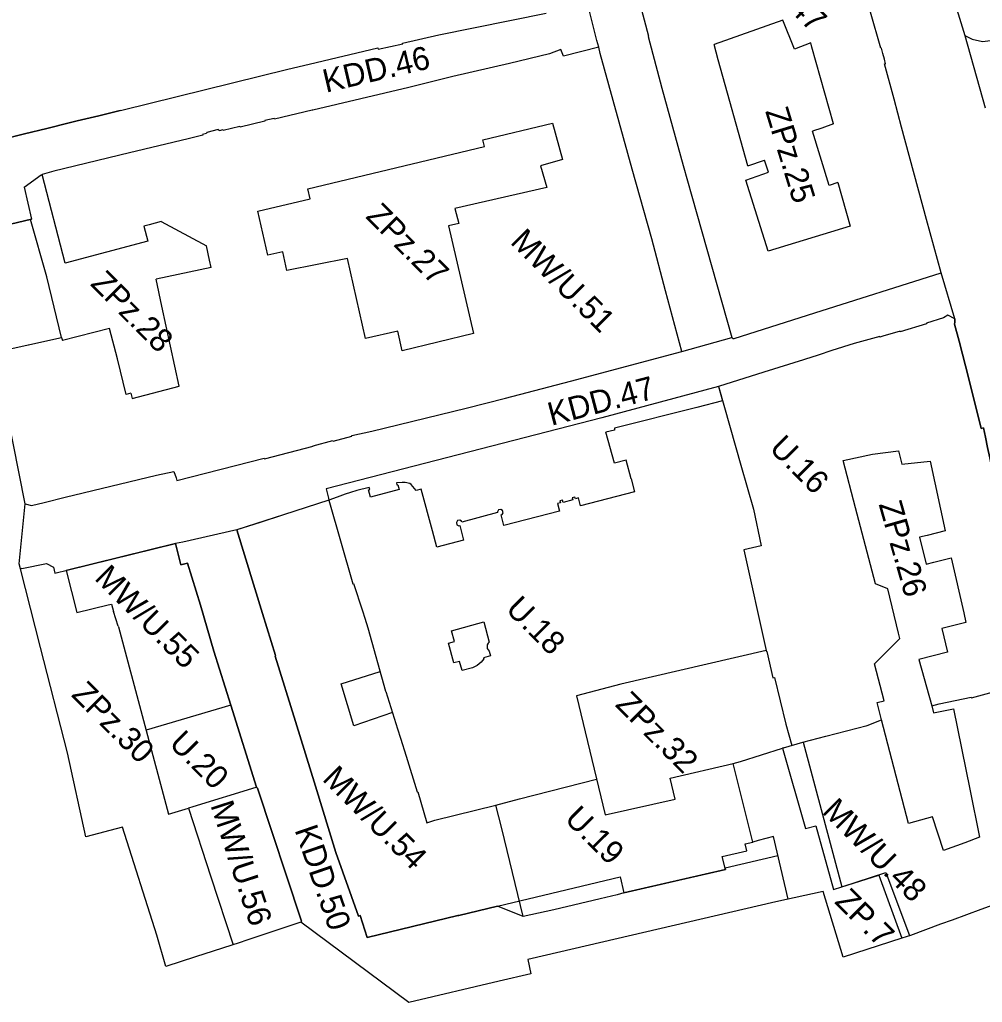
# Model space of a CAD drawing. Extents: x 7423835 to 7425280, y 5546086 to 5547600.
# Drawn here: x 7424089 to 7424338, y 5546086.1 to 5546340.4 of the extents above; entities that cross this region are included whole.
import ezdxf

# ---------------------------------------------------------------- set-up
doc = ezdxf.new("R2010")
doc.units = 0
for name, color, linetype in [('linie rozgraniczające', 7, 'Continuous'), ('nieprzekraczalne linie zabudowy', 7, 'Continuous'), ('obowiazujace linie zabudowy', 7, 'Continuous'), ('przeznaczenia terenów', 7, 'Continuous')]:
    doc.layers.add(name, color=color, linetype=linetype)

msp = doc.modelspace()

# ---------------------------------------------------------------- linework, layer by layer
at = {"layer": 'linie rozgraniczające'}
for p, q in [((7424333.41, 5546336.36), (7424338.71, 5546317.61)), ((7424125.57, 5546288.17), (7424137.31, 5546281.87)), ((7424121.07, 5546286.97), (7424122.14, 5546283.12)), ((7424122.14, 5546283.12), (7424100.75, 5546277.36)), ((7424138.54, 5546276.3), (7424124.28, 5546273.27)), ((7424330.83, 5546262.98), (7424327.32, 5546274.9)), ((7424099.79, 5546258.14), (7424100.11, 5546257.41)), ((7424260.27, 5546254.53), (7424273.2, 5546258.16)), ((7424089.56, 5546198.36), (7424089.18, 5546198.27)), ((7424112.78, 5546189.17), (7424113.24, 5546187.26)), ((7424114.51, 5546183.42), (7424113.24, 5546187.26)), ((7424287.17, 5546158.08), (7424288.73, 5546152.6)), ((7424161.76, 5546107.08), (7424161.88, 5546106.73))]:
    msp.add_line(p, q, dxfattribs=at)
for points in [[(7424329.68, 5546348.73), (7424333.41, 5546336.36), (7424335.31, 5546335.37), (7424338.04, 5546334.78), (7424340.75, 5546335.13), (7424350.4, 5546337.18), (7424412.55, 5546351.75), (7424415.01, 5546352.54), (7424417.37, 5546354.37), (7424418.62, 5546356.9), (7424418.49, 5546360.03), (7424406.49, 5546406.68), (7424405.05, 5546415.06), (7424405.06, 5546424.89), (7424402.17, 5546436.72)], [(7424249.04, 5546346.02), (7424251.62, 5546336.13), (7424251.53, 5546336.1), (7424255.07, 5546322.72), (7424260.57, 5546302.67), (7424262.83, 5546294.73), (7424273.2, 5546258.16), (7424273.42, 5546257.91), (7424273.8, 5546257.89), (7424294.65, 5546264.53), (7424327.32, 5546274.9), (7424323.56, 5546288.69), (7424317.03, 5546312.59), (7424315.21, 5546319.84), (7424312.69, 5546328.97), (7424312.94, 5546329.01), (7424312.64, 5546330.18), (7424312.27, 5546331.62), (7424311.89, 5546333.06), (7424311.89, 5546333.06), (7424311.68, 5546333), (7424309.04, 5546342.36)], [(7424238.77, 5546333.3), (7424238.31, 5546335.04), (7424235.68, 5546345.4)], [(7424115.02, 5546316.87), (7424115.45, 5546316.98), (7424158.31, 5546327.57), (7424163.88, 5546328.94), (7424181.66, 5546333.14), (7424181.75, 5546332.8), (7424188.09, 5546334.17), (7424188.05, 5546334.33), (7424197.38, 5546336.47), (7424225.16, 5546342.14)], [(7424293.58, 5546334.44), (7424289.38, 5546332.75), (7424286.35, 5546340.29), (7424268.59, 5546334.03)], [(7424090.45, 5546215.13), (7424092.07, 5546214.65), (7424095.33, 5546215.47), (7424100.76, 5546216.84), (7424124.35, 5546222.55), (7424124.35, 5546222.55), (7424128.91, 5546223.5), (7424129.47, 5546221.83), (7424129.62, 5546221.17), (7424152.27, 5546226.94), (7424152.3, 5546226.77), (7424164.89, 5546230.01), (7424164.88, 5546230.1), (7424170.02, 5546231.5), (7424170.04, 5546231.37), (7424174.92, 5546232.62), (7424174.89, 5546232.76), (7424180.08, 5546233.94), (7424204.45, 5546239.88), (7424214.64, 5546242.5), (7424231.44, 5546246.9), (7424260.27, 5546254.53), (7424256.07, 5546270.24), (7424252.47, 5546283.71), (7424247.4, 5546301.73), (7424239.13, 5546331.68), (7424238.77, 5546333.3)], [(7424238.77, 5546333.3), (7424229.63, 5546330.99), (7424228.94, 5546332.69), (7424226.05, 5546331.54), (7424215.65, 5546329.09), (7424201.04, 5546325.68), (7424189.62, 5546322.89), (7424164.83, 5546317), (7424164.66, 5546316.99), (7424154.88, 5546314.7), (7424154.84, 5546314.84), (7424152.39, 5546314.29), (7424152.42, 5546314.12), (7424146.02, 5546312.63), (7424145.98, 5546312.78), (7424141.62, 5546311.77), (7424141.57, 5546311.94), (7424140.6, 5546311.68), (7424140.56, 5546311.84), (7424140.41, 5546311.8), (7424140.37, 5546311.95), (7424137.39, 5546311.25), (7424137.42, 5546311.11), (7424137.26, 5546311.08), (7424137.29, 5546310.93), (7424136.3, 5546310.7), (7424136.35, 5546310.53), (7424132.6, 5546309.54), (7424117.44, 5546305.93), (7424097.85, 5546301.25), (7424094.84, 5546300.38)], [(7424277.34, 5546302.63), (7424269.69, 5546330.05), (7424268.59, 5546334.03)], [(7424299.45, 5546313.44), (7424293.9, 5546333.31), (7424293.58, 5546334.44)], [(7424115.02, 5546316.87), (7424109.46, 5546315.54), (7424103.89, 5546314.21), (7424101.84, 5546313.69), (7424096.03, 5546312.29), (7424090.22, 5546310.9), (7424084.12, 5546309.33), (7424081.83, 5546308.77), (7424078.92, 5546308.05), (7424076, 5546307.33), (7424061.81, 5546302.23), (7424054.03, 5546298.9), (7424039.51, 5546289.67), (7424007.29, 5546269.71)], [(7424299.45, 5546313.44), (7424296.45, 5546312.37), (7424294.04, 5546311.52)], [(7424300.61, 5546298.29), (7424298.38, 5546297.52), (7424294.04, 5546311.52)], [(7424300.61, 5546298.29), (7424303.78, 5546286.94), (7424282.54, 5546280.5), (7424276.77, 5546298.89), (7424282.68, 5546300.95), (7424281.64, 5546304.08)], [(7424277.34, 5546302.63), (7424281.64, 5546304.08), (7424281.64, 5546304.08)], [(7424090.16, 5546297.07), (7424094.56, 5546300.3), (7424094.84, 5546300.38)], [(7424100.75, 5546277.36), (7424100.75, 5546277.36), (7424094.84, 5546300.38)], [(7424090.16, 5546297.07), (7424092.06, 5546288.77), (7424091.83, 5546288.66)], [(7424076.76, 5546285.36), (7424081.09, 5546286.44), (7424081.14, 5546286.23), (7424092.06, 5546288.77)], [(7424358.85, 5546117.82), (7424337.57, 5546110.13), (7424330.13, 5546107.4), (7424327.17, 5546106.31), (7424319.35, 5546103.44), (7424317.19, 5546102.74), (7424301.95, 5546097.81), (7424296.8, 5546114.75), (7424284.6, 5546112.07), (7424220.42, 5546097.17), (7424221.18, 5546093.49), (7424212.98, 5546091.55), (7424189.62, 5546086.1), (7424161.71, 5546106.86), (7424160.13, 5546106.33), (7424147.53, 5546102.08), (7424146.06, 5546101.58), (7424134.43, 5546097.87), (7424126.76, 5546095.42), (7424124.43, 5546103.47), (7424115.62, 5546131.45), (7424106.15, 5546128.94), (7424101.33, 5546150.7), (7424094.35, 5546177.91), (7424089.18, 5546198.28), (7424088.86, 5546199.57), (7424090.45, 5546215.13), (7424082.61, 5546254.35), (7424099.79, 5546258.14), (7424096, 5546273.89), (7424091.83, 5546288.66), (7424081.26, 5546286.15)], [(7424125.57, 5546288.17), (7424122.49, 5546287.35), (7424121.07, 5546286.97)], [(7424138.54, 5546276.3), (7424138.12, 5546278.2), (7424137.31, 5546281.87)], [(7424130.23, 5546245.53), (7424125.78, 5546266.29), (7424124.28, 5546273.27)], [(7424330.83, 5546262.98), (7424329.03, 5546263.97), (7424327.94, 5546263.23), (7424323.51, 5546261.83), (7424323.56, 5546261.7), (7424316.73, 5546259.62), (7424316.69, 5546259.77), (7424312.21, 5546258.49), (7424311.48, 5546258.28), (7424311.44, 5546258.4), (7424304.84, 5546256.62), (7424299.07, 5546254.78), (7424295.54, 5546253.62), (7424295.54, 5546253.62), (7424292.01, 5546252.47), (7424291.68, 5546252.37), (7424281.48, 5546249.15), (7424269.73, 5546245.48)], [(7424330.83, 5546262.98), (7424330.85, 5546262.16), (7424330.78, 5546261.63), (7424331.94, 5546257.17), (7424334.47, 5546247.48), (7424337.68, 5546234.64), (7424338.27, 5546234.77), (7424338.75, 5546232.4), (7424339.32, 5546229.72), (7424339.89, 5546227.04), (7424340.5, 5546224), (7424341.1, 5546220.95), (7424341.32, 5546219.63), (7424341.36, 5546219.32), (7424341.6, 5546219.34), (7424342.73, 5546213.99), (7424342.58, 5546213.96), (7424345.8, 5546198.29), (7424345.95, 5546198.32), (7424347.03, 5546193.01), (7424346.88, 5546192.97), (7424351.54, 5546169.38), (7424348.75, 5546168.82), (7424348.79, 5546168.6)], [(7424117.76, 5546243.79), (7424116.58, 5546243.45), (7424114.26, 5546252.68), (7424112.26, 5546260.51), (7424100.11, 5546257.41)], [(7424117.76, 5546243.79), (7424118.12, 5546242.4), (7424130.23, 5546245.53)], [(7424269.73, 5546245.48), (7424239.57, 5546237.39), (7424168.24, 5546219.03), (7424168.88, 5546216.62), (7424168.94, 5546216.05), (7424175.14, 5546194.42), (7424175.32, 5546194.47), (7424177.62, 5546187.39), (7424178.27, 5546185.49), (7424179.01, 5546183.02), (7424183.64, 5546166.67), (7424183.68, 5546166.55), (7424186.72, 5546156.85), (7424187.48, 5546154.48), (7424188.96, 5546149.77), (7424191.82, 5546140.54), (7424191.98, 5546140.58), (7424194.29, 5546132.57), (7424196.38, 5546133.21), (7424212.18, 5546137.17), (7424218.23, 5546138.75), (7424238.19, 5546143.86)], [(7424269.73, 5546245.48), (7424269.79, 5546245.22), (7424275.54, 5546225.13), (7424278.8, 5546213.76), (7424280.81, 5546204.26), (7424276.27, 5546203.18), (7424282.04, 5546177.18), (7424282.11, 5546176.86), (7424282.24, 5546176.89), (7424283.82, 5546170.09), (7424284.2, 5546170.16), (7424287.17, 5546158.08)], [(7424307.97, 5546157.69), (7424308.16, 5546157.74), (7424311.91, 5546159.22), (7424310.76, 5546163.66), (7424312.54, 5546164.12), (7424310.06, 5546173.67), (7424314.38, 5546178.01), (7424316.65, 5546180.3), (7424316.33, 5546181.63), (7424313.53, 5546193.08), (7424310.38, 5546194.43), (7424305.2, 5546214.11), (7424301.99, 5546226.29), (7424309.6, 5546227.93), (7424316.31, 5546228.82), (7424317.14, 5546225.41), (7424324.52, 5546226.14), (7424328.33, 5546208.11), (7424323.7, 5546206.95), (7424321.76, 5546206.46), (7424323.45, 5546199.49), (7424325.39, 5546199.98), (7424329.95, 5546201.12), (7424333.15, 5546186.9), (7424333.71, 5546184.4), (7424327.52, 5546182.81), (7424329, 5546176.73), (7424321.59, 5546174.82), (7424324.88, 5546162.86), (7424325.38, 5546161.03), (7424330.52, 5546162.1), (7424334.73, 5546141.26), (7424337.23, 5546128.87), (7424333.48, 5546127.38), (7424327.92, 5546125.36), (7424325.11, 5546134.08), (7424318.87, 5546132.38), (7424311.91, 5546159.22)], [(7424168.94, 5546216.05), (7424157.21, 5546212.26), (7424145.14, 5546208.38)], [(7424145.14, 5546208.38), (7424131.21, 5546205.18), (7424129.29, 5546204.87)], [(7424219.21, 5546108.3), (7424212.59, 5546111.02), (7424202.55, 5546108.6), (7424202.36, 5546108.57), (7424178.9, 5546102.84), (7424177.03, 5546108.55), (7424176.59, 5546108.42), (7424170.76, 5546124.88), (7424165.49, 5546142.06), (7424160.31, 5546158.82), (7424155.1, 5546175.71), (7424155.14, 5546175.88), (7424151.76, 5546186.73), (7424145.14, 5546208.38)], [(7424089.56, 5546198.36), (7424095.96, 5546199.68), (7424097.76, 5546198.75), (7424098.11, 5546197.14), (7424101.6, 5546198.01), (7424129.29, 5546204.87), (7424130.66, 5546199.34), (7424132.41, 5546199.76), (7424135.76, 5546188.85), (7424139.21, 5546177.01), (7424143.6, 5546162.98), (7424150.29, 5546141.77), (7424150.49, 5546141.56), (7424161.81, 5546107.36), (7424161.88, 5546107.12), (7424161.76, 5546107.08)], [(7424101.05, 5546197.87), (7424103.79, 5546187.03), (7424111.87, 5546188.95), (7424112.78, 5546189.17)], [(7424114.51, 5546183.42), (7424114.57, 5546183.3), (7424127.45, 5546134.81)], [(7424282.04, 5546177.18), (7424244.49, 5546168.47), (7424232.97, 5546165.46), (7424240.41, 5546134.66), (7424258.51, 5546138.72), (7424257.24, 5546144.16), (7424273.55, 5546147.9)], [(7424324.88, 5546162.86), (7424326.81, 5546163.37), (7424335.07, 5546165.09), (7424335.13, 5546164.92), (7424336.09, 5546165.17), (7424348.79, 5546168.6)], [(7424143.6, 5546162.98), (7424121.68, 5546156.51)], [(7424286.58, 5546151.99), (7424291.58, 5546153.4), (7424297.47, 5546155), (7424308.16, 5546157.74)], [(7424287.73, 5546112.76), (7424283.96, 5546129), (7424279.99, 5546127.96), (7424278.59, 5546127.58), (7424273.55, 5546147.9), (7424275.41, 5546148.46), (7424286.32, 5546151.91)], [(7424286.58, 5546151.99), (7424286.32, 5546151.91), (7424292.23, 5546131.12)], [(7424150.29, 5546141.77), (7424150.2, 5546141.74), (7424150.11, 5546141.71), (7424133.8, 5546136.66), (7424132.68, 5546136.33)], [(7424219.21, 5546108.3), (7424213.74, 5546131.05), (7424212.96, 5546134.11), (7424212.18, 5546137.17)], [(7424127.45, 5546134.81), (7424132.68, 5546136.33), (7424138.47, 5546118.57), (7424144.21, 5546100.99)], [(7424292.23, 5546131.12), (7424294.88, 5546131.75), (7424299.51, 5546115.33), (7424301.65, 5546115.98), (7424311.17, 5546119.03), (7424317.19, 5546102.74)], [(7424285.12, 5546123.99), (7424271.45, 5546120.84), (7424271.53, 5546120.52), (7424245.25, 5546114.41), (7424243.52, 5546113.93), (7424239.17, 5546112.92), (7424227.15, 5546110.03), (7424219.21, 5546108.3)]]:
    msp.add_lwpolyline(points, dxfattribs=at)
msp.add_lwpolyline([(7424186.76, 5546259.76), (7424178.42, 5546257.86), (7424173.8, 5546278.64), (7424158.08, 5546275.53), (7424157.06, 5546280.29), (7424153.21, 5546279.47), (7424150.57, 5546290.87), (7424164.15, 5546294.01), (7424163.52, 5546296.67), (7424209.24, 5546307.62), (7424208.76, 5546309.36), (7424226.81, 5546313.66), (7424229.37, 5546304.26), (7424223.71, 5546302.61), (7424225.36, 5546296.97), (7424201.58, 5546291.51), (7424202.55, 5546287.63), (7424199.93, 5546287.03), (7424206.33, 5546259.2), (7424187.89, 5546254.67)], close=True, dxfattribs=at)
at = {"layer": 'nieprzekraczalne linie zabudowy'}
for p, q in [((7424200.69, 5546182.28), (7424209.04, 5546184.61)), ((7424212.59, 5546111.02), (7424244.27, 5546118.61))]:
    msp.add_line(p, q, dxfattribs=at)
for points in [[(7424172.12, 5546168.53), (7424182.22, 5546171.71)], [(7424185.39, 5546161.08), (7424175.46, 5546157.7)]]:
    msp.add_lwpolyline(points, dxfattribs=at)
at = {"layer": 'obowiazujace linie zabudowy'}
msp.add_line((7424175.46, 5546157.7), (7424172.12, 5546168.53), dxfattribs=at)
for points in [[(7424249.04, 5546346.02), (7424251.62, 5546336.13), (7424251.53, 5546336.1), (7424255.07, 5546322.72), (7424260.57, 5546302.67), (7424262.83, 5546294.73), (7424273.2, 5546258.16), (7424273.42, 5546257.91), (7424273.8, 5546257.89), (7424294.65, 5546264.53), (7424327.32, 5546274.9), (7424323.56, 5546288.69), (7424317.03, 5546312.59), (7424315.21, 5546319.84), (7424312.69, 5546328.97), (7424312.94, 5546329.01), (7424312.64, 5546330.18), (7424312.27, 5546331.62), (7424311.89, 5546333.06), (7424311.89, 5546333.06), (7424311.68, 5546333), (7424309.04, 5546342.36)], [(7424115.02, 5546316.87), (7424115.45, 5546316.98), (7424158.31, 5546327.57), (7424163.88, 5546328.94), (7424181.66, 5546333.14), (7424181.75, 5546332.8), (7424188.09, 5546334.17), (7424188.05, 5546334.33), (7424197.38, 5546336.47), (7424225.16, 5546342.14)], [(7424090.45, 5546215.13), (7424092.07, 5546214.65), (7424095.33, 5546215.47), (7424100.76, 5546216.84), (7424124.35, 5546222.55), (7424124.35, 5546222.55), (7424128.91, 5546223.5), (7424129.47, 5546221.83), (7424129.62, 5546221.17), (7424152.27, 5546226.94), (7424152.3, 5546226.77), (7424164.89, 5546230.01), (7424164.88, 5546230.1), (7424170.02, 5546231.5), (7424170.04, 5546231.37), (7424174.92, 5546232.62), (7424174.89, 5546232.76), (7424180.08, 5546233.94), (7424204.45, 5546239.88), (7424214.64, 5546242.5), (7424231.44, 5546246.9), (7424260.27, 5546254.53), (7424256.07, 5546270.24), (7424252.47, 5546283.71), (7424247.4, 5546301.73), (7424239.13, 5546331.68), (7424238.77, 5546333.3)], [(7424238.77, 5546333.3), (7424229.63, 5546330.99), (7424228.94, 5546332.69), (7424226.05, 5546331.54), (7424215.65, 5546329.09), (7424201.04, 5546325.68), (7424189.62, 5546322.89), (7424164.83, 5546317), (7424164.66, 5546316.99), (7424154.88, 5546314.7), (7424154.84, 5546314.84), (7424152.39, 5546314.29), (7424152.42, 5546314.12), (7424146.02, 5546312.63), (7424145.98, 5546312.78), (7424141.62, 5546311.77), (7424141.57, 5546311.94), (7424140.6, 5546311.68), (7424140.56, 5546311.84), (7424140.41, 5546311.8), (7424140.37, 5546311.95), (7424137.39, 5546311.25), (7424137.42, 5546311.11), (7424137.26, 5546311.08), (7424137.29, 5546310.93), (7424136.3, 5546310.7), (7424136.35, 5546310.53), (7424132.6, 5546309.54), (7424117.44, 5546305.93), (7424097.85, 5546301.25), (7424094.84, 5546300.38)], [(7424007.29, 5546269.71), (7424039.51, 5546289.67), (7424054.03, 5546298.9), (7424061.81, 5546302.23), (7424076, 5546307.33), (7424078.92, 5546308.05), (7424081.83, 5546308.77), (7424084.12, 5546309.33), (7424090.22, 5546310.9), (7424096.03, 5546312.29), (7424101.84, 5546313.69), (7424103.89, 5546314.21), (7424109.46, 5546315.54), (7424115.02, 5546316.87)], [(7424092.06, 5546288.77), (7424081.14, 5546286.23), (7424081.09, 5546286.44), (7424076.76, 5546285.36)], [(7424330.83, 5546262.98), (7424329.03, 5546263.97), (7424327.94, 5546263.23), (7424323.51, 5546261.83), (7424323.56, 5546261.7), (7424316.73, 5546259.62), (7424316.69, 5546259.77), (7424312.21, 5546258.49), (7424311.48, 5546258.28), (7424311.44, 5546258.4), (7424304.84, 5546256.62), (7424299.07, 5546254.78), (7424295.54, 5546253.62), (7424295.54, 5546253.62), (7424292.01, 5546252.47), (7424291.68, 5546252.37), (7424281.48, 5546249.15), (7424269.73, 5546245.48)], [(7424348.79, 5546168.6), (7424348.75, 5546168.82), (7424351.54, 5546169.38), (7424346.88, 5546192.97), (7424347.03, 5546193.01), (7424345.95, 5546198.32), (7424345.8, 5546198.29), (7424342.58, 5546213.96), (7424342.73, 5546213.99), (7424341.6, 5546219.34), (7424341.36, 5546219.32), (7424341.32, 5546219.63), (7424341.1, 5546220.95), (7424340.5, 5546224), (7424339.89, 5546227.04), (7424339.32, 5546229.72), (7424338.75, 5546232.4), (7424338.27, 5546234.77), (7424337.68, 5546234.64), (7424334.47, 5546247.48), (7424331.94, 5546257.17), (7424330.78, 5546261.63), (7424330.85, 5546262.16), (7424330.83, 5546262.98)], [(7424269.73, 5546245.48), (7424270.78, 5546241.75), (7424264.15, 5546240.05), (7424242.83, 5546234.67), (7424242.88, 5546234.22), (7424240.62, 5546233.63)], [(7424247.14, 5546221.56), (7424245.86, 5546226.39), (7424242.85, 5546225.6), (7424240.62, 5546233.63)], [(7424247.14, 5546221.56), (7424248.01, 5546218.25), (7424234.02, 5546214.61), (7424233.5, 5546216.64), (7424232.72, 5546216.44), (7424232.55, 5546216.88), (7424231.89, 5546216.71), (7424232.07, 5546216.11), (7424229.54, 5546215.45), (7424229.37, 5546216.05), (7424228.72, 5546215.88), (7424228.85, 5546215.38), (7424228.11, 5546215.17), (7424228.64, 5546213.25), (7424214.22, 5546209.53), (7424213.52, 5546212.31), (7424213.75, 5546212.36), (7424214.02, 5546212.82), (7424213.87, 5546213.39), (7424213.43, 5546213.69), (7424212.84, 5546213.54), (7424212.58, 5546213.06), (7424212.62, 5546212.83), (7424203.33, 5546210.4), (7424203.26, 5546210.64), (7424202.8, 5546210.9), (7424202.22, 5546210.76), (7424201.96, 5546210.31), (7424202.1, 5546209.71), (7424202.58, 5546209.46), (7424202.82, 5546209.5), (7424203.78, 5546205.71)], [(7424192.82, 5546218.92), (7424191.5, 5546218.56), (7424190.26, 5546220.14), (7424189.89, 5546220.38), (7424188.67, 5546220.62), (7424187.95, 5546220.67), (7424186.47, 5546220.51), (7424186.54, 5546220.02), (7424186.84, 5546220.05), (7424187.16, 5546218.82), (7424179.76, 5546216.88), (7424179.25, 5546218.77), (7424179.55, 5546218.85), (7424179.42, 5546219.34), (7424176.17, 5546218.56), (7424174.52, 5546218.06), (7424173.22, 5546217.62), (7424171.08, 5546216.83), (7424168.94, 5546216.05)], [(7424203.78, 5546205.71), (7424196.9, 5546203.88), (7424195.78, 5546208.15), (7424192.82, 5546218.92)], [(7424168.94, 5546216.05), (7424163.08, 5546214.16), (7424157.21, 5546212.26), (7424151.17, 5546210.32), (7424145.14, 5546208.38)], [(7424145.14, 5546208.38), (7424151.76, 5546186.73), (7424155.14, 5546175.88), (7424155.1, 5546175.71), (7424160.31, 5546158.82), (7424165.49, 5546142.06), (7424170.76, 5546124.88), (7424176.59, 5546108.42), (7424177.03, 5546108.55), (7424178.9, 5546102.84), (7424202.36, 5546108.57), (7424202.55, 5546108.6), (7424212.59, 5546111.02)], [(7424161.76, 5546107.08), (7424161.88, 5546107.12), (7424161.81, 5546107.36), (7424150.49, 5546141.56), (7424150.29, 5546141.77), (7424143.6, 5546162.98), (7424139.21, 5546177.01), (7424135.76, 5546188.85), (7424132.41, 5546199.76), (7424130.66, 5546199.34), (7424129.29, 5546204.87), (7424101.05, 5546197.87)], [(7424209.04, 5546184.61), (7424210.43, 5546179.32), (7424210.14, 5546179.02), (7424209.9, 5546178.61), (7424209.94, 5546177.71), (7424210.45, 5546176.97), (7424210.73, 5546175.74), (7424208.94, 5546175.27), (7424209.01, 5546175), (7424208.38, 5546174.16), (7424207.33, 5546173.26), (7424206.09, 5546172.63), (7424203.4, 5546171.94)], [(7424203.4, 5546171.94), (7424202.78, 5546174.3), (7424201.31, 5546173.95), (7424199.94, 5546179.09), (7424201.43, 5546179.48), (7424200.69, 5546182.28)], [(7424291.62, 5546153.41), (7424301.65, 5546115.98), (7424313.05, 5546119.72), (7424319.1, 5546103.36)], [(7424271.53, 5546120.52), (7424270.71, 5546123.87), (7424277.06, 5546125.35), (7424276.66, 5546127.09), (7424278.59, 5546127.58)], [(7424245.25, 5546114.41), (7424258.39, 5546117.46), (7424271.53, 5546120.52)], [(7424244.27, 5546118.61), (7424245.25, 5546114.41)]]:
    msp.add_lwpolyline(points, dxfattribs=at)

# ---------------------------------------------------------------- texts
at = {"layer": 'przeznaczenia terenów'}
for s, rotation, p in [('MW/U.47', 314.9764, (7424270.36, 5546360.44)), ('KDD.46', 13.1682, (7424168.19, 5546321.49)), ('ZPz.25', 286.9784, (7424281.78, 5546316.76)), ('ZPz.27', 314.9764, (7424178.27, 5546289.28)), ('MW/U.51', 314.9764, (7424215.64, 5546282.65)), ('ZPz.28', 314.9764, (7424107.04, 5546271.82)), ('KDD.47', 14.7874, (7424226.51, 5546235.29)), ('U.16', 314.9764, (7424282.6, 5546229.21)), ('ZPz.26', 285.8332, (7424311.12, 5546215.02)), ('MW/U.55', 314.9764, (7424108.09, 5546195.66)), ('U.18', 314.9764, (7424214.42, 5546187.58)), ('ZPz.30', 314.9764, (7424102.13, 5546165.5)), ('ZPz.32', 314.9764, (7424242.79, 5546162.91)), ('U.20', 314.9764, (7424127.37, 5546152.78)), ('MW/U.54', 314.9764, (7424167.02, 5546143.65)), ('MW/U.56', 288.2063, (7424138.29, 5546137.13)), ('MW/U.48', 314.9764, (7424296.28, 5546135.28)), ('U.19', 314.9764, (7424229.65, 5546133.28)), ('KDD.50', 288.9925, (7424160.04, 5546130.76)), ('ZP.7', 314.9764, (7424299.51, 5546111.92))]:
    msp.add_text(s, height=6, rotation=rotation, dxfattribs=at).set_placement(p)

doc.saveas('drawing.dxf')
